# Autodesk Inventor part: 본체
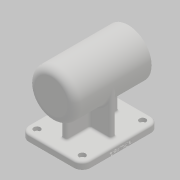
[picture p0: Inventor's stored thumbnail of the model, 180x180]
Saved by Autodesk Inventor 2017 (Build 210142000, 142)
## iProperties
Part Number: 본체
Material: 일반
Document SubType Name: Modeling
Designer: mrc
Density: 1 g/cm^3
Appearance: 기본값
Mass: 380.103 g
Surface Area: 757.984 cm^2
Volume: 380.103 cm^3
Author: mrc
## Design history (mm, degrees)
sketch "스케치1"
  geometry: L1 (-56, 0)-(56, 0); L2 (-56, 0)-(-56, 34); L3 (-56, 34)-(56, 34); L4 (56, 34)-(56, 21); L5 (56, 21)-(41, 21); L6 (41, 21)-(41, 24); L7 (41, 24)-(-13, 24); L8 (-13, 24)-(-13, 21); L9 (-13, 21)-(-25, 21); L10 (-25, 21)-(-25, 17.5); L11 (-25, 17.5)-(-43, 17.5); L12 (-43, 17.5)-(-43, 16); L13 (-43, 16)-(-47, 16); L14 (-47, 16)-(-47, 10.5); L15 (-47, 10.5)-(-50, 10.5); L16 (-50, 10.5)-(-50, 0); L17 (-50, 0)-(-56, 0); 2 further points
  constraints: 34 end point, 13 perpendicular, 3 point on line, 2 coincident, 2 horizontal, 1 horizontal alignment, 1 midpoint, 1 vertical
  dimensions: "d0" = 112 distance of L1.start L1.end; "d1" = 112 distance between parallel lines of L4 L2; "d2" = 3 distance between parallel lines of L14 L16; "d3" = 4 distance between parallel lines of L12 L14; "d4" = 18 distance between parallel lines of L10 L12; "d5" = 12 distance between parallel lines of L8 L10; "d6" = 54 distance between parallel lines of L6 L8; "d9" = 15 distance of L4.end L5.end; "d10" = 42 diameter of L5 L1; "d11" = 48 diameter of L7 L1; "d12" = 35 diameter of L11 L1; "d13" = 32 diameter of L13 L1; "d14" = 21 diameter of L15 L1; "d15" = 68 diameter of L3 L1
revolve "회전1" sketch "스케치1" stored, may be unused: angle "d16" = 90 deg
sketch "스케치2"
  geometry: 2 further points
  constraints: 1 vertical alignment
  dimensions: "d17" = 26 distance of point (0, 0) point (0, -26)
hole "구멍1" sketch "스케치2" at (0, -26) diameter "d18" = 3.242; stored, may be unused: countersink angle "d22" = 90 deg, drill point angle "d24" = 118 deg; dims "d19" = 8, "d20" = 4, "d21" = 2, "d23" = 11
node "작업 평면1"
sketch "스케치3"
  geometry: L1 (-45, -56)-(45, -56); L2 (45, -56)-(45, 56); L3 (45, 56)-(-45, 56); L4 (-45, 56)-(-45, -56); 3 further points
  constraints: 8 end point, 2 midpoint, 2 parallel, 1 horizontal, 1 horizontal alignment, 1 perpendicular, 1 vertical alignment
  dimensions: "d29" = 112 distance between parallel lines of L3 L1; "d30" = 90 distance between parallel lines of L2 L4
extrude "돌출1" join sketch "스케치3" distance "d31" = 10; taper "d32" = 0 deg
fillet "모깎기1" dims "d33" = 12
sketch "스케치4"
  geometry: A1 r 12 centre (-33, 44) between (-33, 56) and (-45, 44) reference; A2 r 12 centre (-33, -44) between (-45, -44) and (-33, -56) reference; A3 r 12 centre (33, -44) between (33, -56) and (45, -44) reference; A4 r 12 centre (33, 44) between (45, 44) and (33, 56) reference; 5 further points
  constraints: 4 coincident
hole "구멍2" sketch "스케치4" at (-33, 44), (33, 44), (33, -44), (-33, -44) diameter "d34" = 5.5; stored, may be unused: countersink angle "d38" = 90 deg, drill point angle "d40" = 118 deg; dims "d35" = 8, "d36" = 9.5, "d37" = 5.4, "d39" = 11
sketch "스케치5"
  geometry: L1 (-4, -38)-(4, -38); L2 (4, -38)-(4, 38); L3 (4, 38)-(-4, 38); L4 (-4, 38)-(-4, -38); L5 (-34, -4)-(34, -4); L6 (34, -4)-(34, 4); L7 (34, 4)-(-34, 4); L8 (-34, 4)-(-34, -4); 5 further points
  constraints: 16 end point, 4 midpoint, 4 parallel, 2 horizontal, 2 horizontal alignment, 2 perpendicular, 2 vertical alignment
  dimensions: "d41" = 8 distance between parallel lines of L2 L4; "d42" = 76 distance between parallel lines of L1 L3; "d43" = 8 distance between parallel lines of L7 L5; "d44" = 68 distance between parallel lines of L6 L8
extrude "돌출2" join sketch "스케치5" stored distance "d45" = 10; taper "d46" = 0 deg
node "작업 평면2"
sketch "스케치6"
  geometry: L1 (0, 100)-(-10, 100) reference; L2 (0, 100)-(0, 88) reference; 2 further points
  constraints: 1 other
  dimensions: "d48" = 56 distance from line of L1 point (-3, 44); "d49" = 3 distance from line of L2 point (-3, 44)
feature "엠보싱1" sketch "스케치6" dims "d50" = 0.5, "d51" = 0
chamfer "모따기1" distance "d52" = 1; stored, may be unused: second distance "d53" = 2, angle "d54" = 45 deg
fillet "모깎기2" dims "d55" = 10
fillet "모깎기3" dims "d56" = 0.3
fillet "모깎기4" dims "d57" = 3
fillet "모깎기5" dims "d58" = 3
fillet "모깎기6" dims "d59" = 3
fillet "모깎기7" dims "d60" = 3
node "솔리드1"
pattern_circular "원형 패턴1" dims angle "d26" = 360 deg
other parameters: "d28" = -74, "d47" = 5
